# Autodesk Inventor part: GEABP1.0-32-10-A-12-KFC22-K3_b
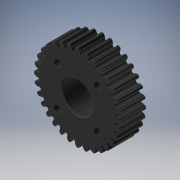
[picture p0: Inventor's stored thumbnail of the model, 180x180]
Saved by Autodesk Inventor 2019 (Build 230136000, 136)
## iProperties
Created: 2022-11
Part Number: GEABP1.0-32-10-A-12-KFC22-K3_b
Material: Generic
Catalog Web Link: www.cadenas.de
Description: GEABM, GEABMS, GEABMT, GEABP, GEABPS, GEABPT, GEABA, GEABAS, GEABAT_body-Plastic Spur Gears - Pressure Angle 20 Degrees, Module 0.5/0.8/1.0/1.5/2.0/2.5/3.0
Vendor: MISUMI
Document SubType Name: Modeling
Designer: psAdmin
Manufacturer: MISUMI
Mass: 6.51664 g
Surface Area: 40.015 cm^2
Volume: 6.51664 cm^3
Density: 1 g/cm^3
Appearance: PSOLRGB-175-175-175
Category: PARTsolutions
Company: MISUMI
Title: GEABP1.0-32-10-A-12-KFC22-K3
Author: Cadenas PARTsolutions
Comments: Plastic Spur Gears - Pressure Angle 20 Degrees, Module 0.5/0.8/1.0/1.5/2.0/2.5/3.0
PSOL_IDENT_0: {$CADENAS_DATA/23d-libs/misumi/metric/54_spur_gears/geabms20/geabms20.prj},408 {VTYP=3D},{NB=GEABP1.
PSOL_IDENT_1: 0-32-10-A-12-KFC22-K3_b},{LINA=GEABP1.0-32-10-A-12-KFC22-K3},{NN=GEABM, GEABMS, GEABMT, GEABP, GEABP
PSOL_IDENT_2: S, GEABPT, GEABA, GEABAS, GEABAT_body},{DATE=17.10.2022 23:48:33},{GEOMDATE=14.09.2022 05:11:00},{VE
PSOL_IDENT_3: RSION=},{LINEID=30},{WBVAR=MATSG,MATCR,NT,B,TS,PS,ALT1,ALT2,TPC,ALT11,ALT10,BS,ALT3,Z,J,ALT4,Q,R,S,T
PSOL_IDENT_4: ,ALT5,LFC,LTC,MALT5,ALT6,KFC,KTC,K},{WBNUMERIC=NT,B,BS,Z,J,Q,R,S,T,LFC,LTC,KFC,KTC,K}  {NB=GEABP1.0-
PSOL_IDENT_5: 32-10-A-12-KFC22-K3_b},{LINA=GEABP1.0-32-10-A-12-KFC22-K3},{KT=DUMMY},{PN=GEABP1.0-32-10-A-12-KFC22-
PSOL_IDENT_6: K3},{TYPE=GEABP},{MATSG=PW},{MATSGALG='MCN','MC Nylon','PW','Polyacetal White','PB','Polyacetal Blue'
PSOL_IDENT_7: },{MATCR=},{MATCRALG='','-','S45C','1045 Carbon Steel','SUS304','304 Stainless Steel'},{MOD=1.0},{MO
PSOL_IDENT_8: D1=1.0},{NT=32},{NTALG=15,16,18,20,22,24,25,26,28,30,32,35,36,40,45,48,50,55,60,70,75,80,90,100,120}
PSOL_IDENT_9: ,{B=10},{BALG=10,15},{TS=A},{TSALG='A','A','B','B'},{TSPN=-A},{PS=12},{PSALG='10','10','11','11','12'
PSOL_IDENT_10: ,'12','13','13','14','14','15','15','16','16','17','17','18','18'},{PSCRL='10','10','11','11','12','
PSOL_IDENT_11: 12','13','13','14','14','15','15','16','16','17','17','18','18'},{PSCRW='10','10','12','12'},{DD=32.
PSOL_IDENT_12: 0},{DD05=16},{DD08=25.6},{DD10=32},{DD15=48},{DD20=64},{DD25=80},{DD30=96},{D=34.0},{D05=17},{D08=27
PSOL_IDENT_13: .2},{D10=34},{D15=51},{D20=68},{D25=85},{D30=102},{G=29.50},{G05=14.75},{G08=23.6},{G10=29.5},{G15=4
PSOL_IDENT_14: 4.25},{G20=59},{G25=73.75},{G30=88.5},{H=0.0},{L=0},{LL1=0},{LL2=0.0},{M=-},{M3D=0},{P=12.00},{DD1=0
PSOL_IDENT_15: },{CIFR=15},{CIFM=0},{CIFK=0},{CIFTAP=0},{ALT1=},{ALT1ALG='','Not applicable'},{ALT1PN=},{ALT2=},{AL
PSOL_IDENT_16: T2ALG='','Not applicable'},{TPC=N/A},{TPCALG='N/A'},{ALT2PN=},{KC=0},{ALT11=},{ALT11ALG='','Not appl
PSOL_IDENT_17: icable'},{ALT11PN=},{DEG=0},{ALT10=},{ALT10ALG= '','Not applicable' },{ALT10PN=},{BS=0.0},{BSALG=0},
PSOL_IDENT_18: {BSMIN=3},{BSMINALG=3.000},{BSMAX=0},{LL13D=0},{LL23D=0},{LBS=10},{ALT3=},{ALT3ALG= '','w/o Stepped
PSOL_IDENT_19: Hole','DHL','with DHL (Stepped Hole)','DHR','with DHR (Stepped Hole)' },{ALT3PN=},{ZJPN=},{ALT31=1},
PSOL_IDENT_20: {ALT32=1},{Z=0},{ZALG=0},{ZMINL=14},{ZMAXL=25},{ZMINR=14},{ZMAXR=25},{ZPN=},{J=0.0},{JALG=0},{JMIN=2
PSOL_IDENT_21: },{JMAX=0},{JPN=},{ALT4=},{ALT4ALG= '','w/o WDH (Both Ends Stepped Hole)','WDH','with WDH (Both Ends
PSOL_IDENT_22: Stepped Hole)' },{ALT4PN=},{QRSTPN=},{LB=10.000},{Q=0},{QALG=0},{QMIN=14},{QMAX=25},{QPN=},{R=0},{R
PSOL_IDENT_23: ALG=0},{RMIN=14},{RMAX=25},{RPN=},{S=0},{SALG=0},{SMIN=3},{SMAX=4},{SPN=},{T=0},{TALG=0},{TMIN=3},{T
PSOL_IDENT_24: MAX=0},{TPN=},{ALT5=},{ALT5ALG= '','w/o Side Slotted Hole','LFC','with LFC (Side Slotted Hole)','LTC'
PSOL_IDENT_25: ,'with LTC (Side Slotted Hole)' },{LFC=0},{LFCALG=0},{LTC=0},{LTCALG=0},{LPCDMIN=20},{LPCDMAX=22},{L
PSOL_IDENT_26: CMAX=25},{MALT5=N/A},{MALT5ALG= 'N/A' },{LCMAX2=22},{C=0.0},{ALT5PN=},{ALT6=KFC},{ALT6ALG= '','w/o S
PSOL_IDENT_27: ide Through Hole','KFC','with KFC (Side Through Hole)','KTC','with KTC (Side Through Hole)' },{ALT6P
PSOL_IDENT_28: N=-KFC},{KFTCPN=22-K3},{KFC=22},{KFCALG=[19:22/1]},{KFCPN=22},{KTC=0},{KTCALG=[0]},{KTCPN=},{KPCDMIN
PSOL_IDENT_29: 1=19},{KPCDMAX1=-7},{KPCDMIN2=7},{KPCDMAX2=22},{K=3.0},{KALG=[3:3.5/0.5]},{KPCD=22},{KPN=-K3},{SCREW=
PSOL_IDENT_30: 0},{SCREWL=0},{AG=0},{PCD=22},{SHN=4},{SHDEG1=45},{SHDEG2=90},{PZQRDD2=12},{D1=2.8125},{D2=5.625},{D
PSOL_IDENT_31: 3=20},{D4=0.1},{D5=5.333333},{D6=4.923077},{D7=0.85},{D8=0.5},{D9=0.821781},{S1=15},{S2=0.5},{KR=15}
NB: GEABP1.0-32-10-A-12-KFC22-K3_b
NN: GEABM, GEABMS, GEABMT, GEABP, GEABPS, GEABPT, GEABA, GEABAS, GEABAT_body
NT: 32
NBSYN: $PN._b
LINA: GEABP1.0-32-10-A-12-KFC22-K3
CATALOG: Misumi
PN: GEABP1.0-32-10-A-12-KFC22-K3
MATSG: Polyacetal White
MATCR: -
MOD: 1.0
B: 10
TS: A
PS: 12
DD: 32
D: 34
G: 29.5
H: 0
L: 0
LL1: 0
LL2: 0
M: -
DD1: 0
ALT1: Not applicable
ALT2: Not applicable
TPC: N/A
ALT11: Not applicable
ALT10: Not applicable
BS: 0
ALT3: w/o Stepped Hole
Z: 0
J: 0
ALT4: w/o WDH (Both Ends Stepped Hole)
Q: 0
R: 0
S: 0
T: 0
ALT5: w/o Side Slotted Hole
LFC: 0
LTC: 0
MALT5: N/A
C: 0
ALT6: with KFC (Side Through Hole)
KFC: 22
KTC: 0
K: 3
SUPPLIER: MISUMI
ARTICLENO: GEABP1.0-32-10-A-12-KFC22-K3_b
BOMINFO: GEABP1.0-32-10-A-12-KFC22-K3
CREATOR: CADENAS GmbH
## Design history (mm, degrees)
sketch "_____3"
  geometry: L1 (10, 0)-(0, 0); L2 (0, 0)-(0, 16.5); L3 (0, 16.5)-(0.67, 19); L4 (0.67, 19)-(9.33, 19); L5 (9.33, 19)-(10, 16.5); L6 (10, 16.5)-(10, 0); L7 (10, 0)-(0, 0)
  constraints: 14 end point
revolve "Revolution1" sketch "_____3" stored, may be unused: angle "d0" = 360 deg
sketch "_____12"
  geometry: C1 r 68 at (0, 0); A1 r 17 centre (0, 0) between (-16.997, 0.293) and (-16.997, -0.293); A2 r 0.1 centre (-16.897, -0.291) between (-16.997, -0.293) and (-16.945, -0.379); A3 r 5.333 centre (-14.405, 4.31) between (-16.945, -0.379) and (-15.981, -0.785); A4 r 0.822 centre (-15.738, 0) between (-15.981, -0.785) and (-15.797, -0.82); A5 r 4.923 centre (-16.156, -5.73) between (-15.074, -0.927) and (-15.797, -0.82); A6 r 0.5 centre (-15.184, -1.415) between (-14.686, -1.368) and (-15.074, -0.927); A7 r 14.75 centre (0, 0) between (-14.686, -1.368) and (-14.671, -1.523); A8 r 0.5 centre (-15.168, -1.575) between (-14.966, -2.032) and (-14.671, -1.523); A9 r 4.923 centre (-16.963, 2.468) between (-15.653, -2.278) and (-14.966, -2.032); A10 r 0.822 centre (-15.435, -3.07) between (-15.653, -2.278) and (-15.827, -2.348); A11 r 5.333 centre (-13.287, -7.037) between (-15.827, -2.348) and (-16.694, -2.934); A12 r 0.1 centre (-16.63, -3.011) between (-16.694, -2.934) and (-16.728, -3.029); A13 r 17 centre (0, 0) between (-16.728, -3.029) and (-16.614, -3.604); A14 r 0.1 centre (-16.516, -3.582) between (-16.614, -3.604) and (-16.546, -3.678); A15 r 5.333 centre (-14.969, 1.417) between (-16.546, -3.678) and (-15.521, -3.888); A16 r 0.822 centre (-15.435, -3.07) between (-15.521, -3.888) and (-15.334, -3.886); A17 r 4.923 centre (-14.727, -8.771) between (-14.604, -3.85) and (-15.334, -3.886); A18 r 0.5 centre (-14.617, -4.35) between (-14.137, -4.207) and (-14.604, -3.85); A19 r 14.75 centre (0, 0) between (-14.137, -4.207) and (-14.092, -4.356); A20 r 0.5 centre (-14.57, -4.504) between (-14.282, -4.913) and (-14.092, -4.356); A21 r 4.923 centre (-17.118, -0.889) between (-14.908, -5.288) and (-14.282, -4.913); A22 r 0.822 centre (-14.54, -6.023) between (-14.908, -5.288) and (-15.065, -5.39); A23 r 5.333 centre (-11.659, -9.494) between (-15.065, -5.39) and (-15.8, -6.134); A24 r 0.1 centre (-15.723, -6.197) between (-15.8, -6.134) and (-15.816, -6.234); A25 r 17 centre (0, 0) between (-15.816, -6.234) and (-15.591, -6.775); A26 r 0.1 centre (-15.5, -6.736) between (-15.591, -6.775) and (-15.51, -6.835); A27 r 5.333 centre (-14.958, -1.53) between (-15.51, -6.835) and (-14.464, -6.841); A28 r 0.822 centre (-14.54, -6.023) between (-14.464, -6.841) and (-14.281, -6.803); A29 r 4.923 centre (-12.733, -11.476) between (-13.572, -6.625) and (-14.281, -6.803); A30 r 0.5 centre (-13.487, -7.118) between (-13.045, -6.884) and (-13.572, -6.625); A31 r 14.75 centre (0, 0) between (-13.045, -6.884) and (-12.971, -7.022); A32 r 0.5 centre (-13.411, -7.26) between (-13.049, -7.604) and (-12.971, -7.022); A33 r 4.923 centre (-16.616, -4.212) between (-13.59, -8.095) and (-13.049, -7.604); A34 r 0.822 centre (-13.086, -8.744) between (-13.59, -8.095) and (-13.724, -8.226); A35 r 5.333 centre (-9.583, -11.587) between (-13.724, -8.226) and (-14.3, -9.099); A36 r 0.1 centre (-14.212, -9.145) between (-14.3, -9.099) and (-14.296, -9.2); A37 r 17 centre (0, 0) between (-14.296, -9.2) and (-13.97, -9.687); A38 r 0.1 centre (-13.888, -9.63) between (-13.97, -9.687) and (-13.879, -9.73); A39 r 5.333 centre (-14.372, -4.419) between (-13.879, -9.73) and (-12.851, -9.531); A40 r 0.822 centre (-13.086, -8.744) between (-12.851, -9.531) and (-12.679, -9.458); A41 r 4.923 centre (-10.25, -13.74) between (-12.019, -9.145) and (-12.679, -9.458); A42 r 0.5 centre (-11.839, -9.612) between (-11.451, -9.297) and (-12.019, -9.145); A43 r 14.75 centre (0, 0) between (-11.451, -9.297) and (-11.352, -9.417); A44 r 0.5 centre (-11.737, -9.737) between (-11.315, -10.004) and (-11.352, -9.417); A45 r 4.923 centre (-15.475, -7.372) between (-11.75, -10.591) and (-11.315, -10.004); A46 r 0.822 centre (-11.128, -11.128) between (-11.75, -10.591) and (-11.855, -10.745); A47 r 5.333 centre (-7.138, -13.233) between (-11.855, -10.745) and (-12.25, -11.714); A48 r 0.1 centre (-12.154, -11.742) between (-12.25, -11.714) and (-12.226, -11.812); A49 r 17 centre (0, 0) between (-12.226, -11.812) and (-11.812, -12.226); A50 r 0.1 centre (-11.742, -12.154) between (-11.812, -12.226) and (-11.714, -12.25); A51 r 5.333 centre (-13.233, -7.138) between (-11.714, -12.25) and (-10.745, -11.855); A52 r 0.822 centre (-11.128, -11.128) between (-10.745, -11.855) and (-10.591, -11.75); A53 r 4.923 centre (-7.372, -15.475) between (-10.004, -11.315) and (-10.591, -11.75); A54 r 0.5 centre (-9.737, -11.737) between (-9.417, -11.352) and (-10.004, -11.315); A55 r 14.75 centre (0, 0) between (-9.417, -11.352) and (-9.297, -11.451); A56 r 0.5 centre (-9.612, -11.839) between (-9.145, -12.019) and (-9.297, -11.451); A57 r 4.923 centre (-13.74, -10.25) between (-9.458, -12.679) and (-9.145, -12.019); A58 r 0.822 centre (-8.744, -13.086) between (-9.458, -12.679) and (-9.531, -12.851); A59 r 5.333 centre (-4.419, -14.372) between (-9.531, -12.851) and (-9.73, -13.879); A60 r 0.1 centre (-9.63, -13.888) between (-9.73, -13.879) and (-9.687, -13.97); A61 r 17 centre (0, 0) between (-9.687, -13.97) and (-9.2, -14.296); A62 r 0.1 centre (-9.145, -14.212) between (-9.2, -14.296) and (-9.099, -14.3); A63 r 5.333 centre (-11.587, -9.583) between (-9.099, -14.3) and (-8.226, -13.724); A64 r 0.822 centre (-8.744, -13.086) between (-8.226, -13.724) and (-8.095, -13.59)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; 1 further point
  constraints: 768 point on circle, 385 centre point
extrude "Extrusion1" cut sketch "_____12" distance "d1" = 10; taper "d2" = 0 deg
sketch "Sketch3"
  geometry: 1 further point
hole "Hole1" sketch "Sketch3" at (0, 0) diameter "d3" = 12; stored, may be unused: countersink angle "d7" = 90 deg, drill point angle "d9" = 0 deg; dims "d4" = 6, "d5" = 4, "d6" = 2, "d8" = 10
sketch "_____5"
  geometry: L1 (500, 0)-(-500, 0); L2 (9.7, 6)-(10, 6); L3 (10, 6)-(10, 6.3); L4 (10, 6.3)-(9.7, 6)
  constraints: 8 end point
revolve "Revolution2" sketch "_____5" stored, may be unused: angle "d10" = 360 deg
sketch "_____13"
  geometry: L1 (500, 0)-(-500, 0); L2 (0, 6.3)-(0, 6); L3 (0, 6)-(0.3, 6); L4 (0.3, 6)-(0, 6.3)
  constraints: 8 end point
revolve "Revolution3" sketch "_____13" stored, may be unused: angle "d11" = 360 deg
sketch "Sketch6"
  geometry: 1 further point
hole "Hole2" sketch "Sketch6" at (-6.111, 9.146) diameter "d12" = 3; stored, may be unused: countersink angle "d16" = 90 deg, drill point angle "d18" = 0 deg; dims "d13" = 6, "d14" = 4, "d15" = 2, "d17" = 10
pattern_linear "Rectangular Pattern1" dims "d21" = 15.55635, "d24" = 15.55635
body "Solid1"
